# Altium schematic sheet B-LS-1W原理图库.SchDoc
size 127 x 99 mm
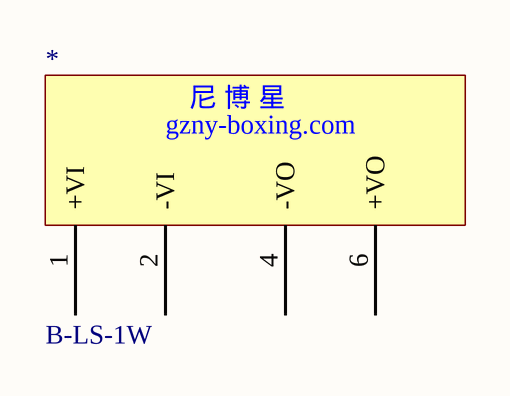
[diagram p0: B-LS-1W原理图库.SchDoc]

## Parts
*  B-LS-1W

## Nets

Not connected (* = marked no-connect by the designer): * 1(+VI) 2(-VI) 4(-VO) 6(+VO)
